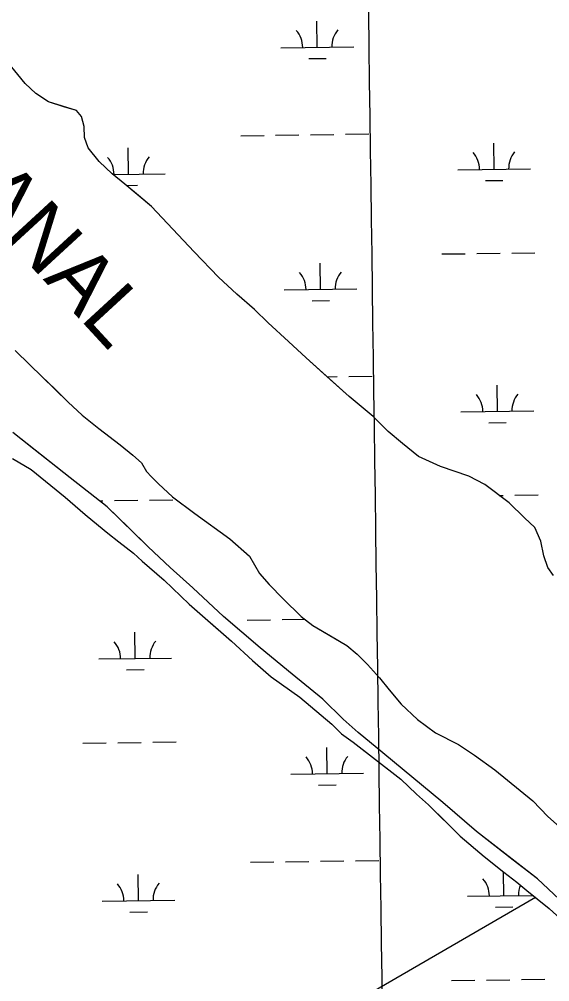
# Model space of a CAD drawing. Extents: x 3753511 to 3791668, y 379550 to 405377.
# Drawn here: x 3783740 to 3784469, y 386459 to 387781 of the extents above; entities that cross this region are included whole.
import ezdxf

# ---------------------------------------------------------------- set-up
doc = ezdxf.new("R2010")
doc.units = 0
for name, color, linetype in [('V-GRID-MAJR', 7, 'Continuous'), ('V-RIVR-IDEN', 7, 'Continuous'), ('V-TOPO-SHOR', 7, 'Continuous'), ('V-WETL-SWMP', 7, 'Continuous')]:
    doc.layers.add(name, color=color, linetype=linetype)

msp = doc.modelspace()

# ---------------------------------------------------------------- linework, layer by layer
at = {"layer": 'V-GRID-MAJR'}
msp.add_spline([(3784253.946, 385328.666), (3784170.23, 391386.958), (3784086.488, 397447.179), (3784002.745, 403507.403), (3784002.718, 403509.328)], degree=3, dxfattribs=at)
at = {"layer": 'V-TOPO-SHOR'}
msp.add_line((3784448.9250000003, 386574.607), (3783909.816065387, 386262.0993850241), dxfattribs=at)
for points in [[(3783829.813, 387618.585), (3783829.0160000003, 387633.663), (3783825.487, 387647.35000000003), (3783818.571, 387655.525), (3783801.393, 387660.88300000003), (3783780.089, 387667.582), (3783762.864, 387679.11), (3783748.366, 387692.715), (3783724.15, 387722.702), (3783697.194, 387751.984), (3783671.6580000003, 387775.106), (3783641.296, 387801.619), (3783616.44, 387825.431), (3783590.18, 387853.348), (3783557.711, 387886.703), (3783523.176, 387921.413), (3783486.5840000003, 387956.108), (3783458.289, 387981.268), (3783433.451, 388002.338), (3783416.889, 388017.298)], [(3784473.772, 387017.135), (3784466.149, 387028.049), (3784460.548, 387043.775), (3784456.284, 387064.313), (3784447.92, 387082.761), (3784434.108, 387096.37), (3784412.702, 387116.78), (3784379.611, 387141.903), (3784357.586, 387153.397), (3784318.4080000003, 387166.68200000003), (3784288.1410000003, 387180.582), (3784266.346, 387198.11100000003), (3784246.755, 387214.556), (3784225.898, 387235.245), (3784192.921, 387262.838), (3784158.552, 387293.846), (3784134.119, 387315.879), (3784109.819, 387338.325), (3784081.7970000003, 387363.896), (3784063.012, 387382.132), (3784038.997, 387403.34500000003), (3784013.4590000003, 387426.878), (3783980.292, 387461.735), (3783921.694, 387523.966), (3783903.7600000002, 387538.916), (3783885.133, 387554.549), (3783867.887, 387568.819), (3783849.936, 387585.826), (3783834.718, 387604.22500000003), (3783829.813, 387618.585)], [(3783734.62, 387325.822), (3783754.645, 387306.087), (3783771.215, 387290.441), (3783789.1720000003, 387272.748), (3783807.127, 387255.055), (3783826.454, 387237.373), (3783849.215, 387219.029), (3783878.86, 387196.624), (3783896.106, 387182.353), (3783907.842, 387171.47000000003), (3783914.782, 387159.866), (3783921.694, 387152.375), (3783931.363, 387142.847), (3783950.69, 387125.165), (3783981.0270000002, 387102.08), (3784029.272, 387067.471), (3784056.186, 387043.673), (3784063.133, 387031.38300000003), (3784070.074, 387019.779), (3784083.2120000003, 387004.794), (3784102.5530000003, 386985.053), (3784127.416, 386960.55700000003), (3784143.273, 386948.332), (3784167.3740000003, 386934.11100000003), (3784190.099, 386920.568), (3784203.896, 386909.015), (3784218.398, 386894.724), (3784234.989, 386876.337), (3784248.1350000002, 386859.978), (3784264.736, 386840.218), (3784286.83, 386819.128), (3784311.648, 386800.80100000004), (3784343.304, 386784.58), (3784365.348, 386770.34500000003), (3784392.923, 386749.979), (3784445.341, 386707.174), (3784466.0670000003, 386686.074), (3784489.531, 386664.994)], [(3784481.302, 386572.379), (3784451.616, 386600.26900000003), (3784418.5160000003, 386626.078), (3784368.179, 386665.471), (3784321.951, 386704.893), (3784239.1750000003, 386773.527), (3784205.377, 386801.386), (3784184.6720000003, 386819.74700000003), (3784157.048, 386846.967), (3784114.97, 386881.621), (3784070.828, 386917.631), (3784020.463, 386960.452), (3783978.35, 386999.905), (3783947.294, 387027.787), (3783916.916, 387056.356), (3783889.983, 387082.896), (3783860.977, 387111.476), (3783809.953, 387150.865), (3783760.3000000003, 387190.26300000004), (3783731.335, 387213.36)], [(3783730.776, 387177.43200000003), (3783756.253, 387162.537), (3783803.154, 387124.489), (3783830.753, 387100.697), (3783848.6890000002, 387085.745), (3783861.796, 387074.87200000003), (3783876.964, 387063.33), (3783896.961, 387047.71), (3783908.698, 387036.826), (3783939.057, 387010.311), (3783973.578, 386977.658), (3783999.111, 386955.222), (3784031.545, 386926.667), (3784060.534, 386900.143), (3784086.069, 386877.705), (3784125.3510000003, 386849.885), (3784169.504, 386812.505), (3784182.628, 386799.576), (3784198.481, 386788.037), (3784221.235, 386770.38), (3784263.989, 386737.10000000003), (3784285.392, 386716.689), (3784301.957, 386701.731), (3784326.127, 386677.912), (3784345.464, 386658.858), (3784378.578, 386630.993), (3784405.477, 386609.253)], [(3784405.477, 386609.253), (3784423.403, 386595.673), (3784437.2, 386584.12), (3784448.9250000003, 386574.607), (3784467.546, 386559.663), (3784488.255, 386540.619)]]:
    msp.add_lwpolyline(points, dxfattribs=at)
at = {"layer": 'V-WETL-SWMP'}
for p, q in [((3784149.380095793, 387742.5315603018), (3784148.893345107, 387778.52826950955)), ((3784099.384666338, 387741.8555176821), (3784199.375525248, 387743.20760292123)), ((3783748.366, 387692.71500000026), (3783724.15, 387722.7020000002)), ((3784137.5898329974, 387726.9397206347), (3784161.5876391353, 387727.26422109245)), ((3783762.864, 387679.1100000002), (3783748.366, 387692.71500000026)), ((3783780.089, 387667.5820000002), (3783762.864, 387679.1100000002)), ((3783818.571, 387655.525), (3783780.089, 387667.5820000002)), ((3783825.488, 387647.3490000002), (3783818.571, 387655.525)), ((3783829.0160000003, 387633.66300000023), (3783825.488, 387647.3490000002)), ((3783829.813, 387618.586), (3783829.0160000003, 387633.66300000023)), ((3783834.718, 387604.22500000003), (3783829.813, 387618.586)), ((3784044.1693247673, 387621.02691414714), (3784076.166399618, 387621.4595814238)), ((3784092.164937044, 387621.6759150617), (3784124.1620118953, 387622.10858233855)), ((3784140.1605493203, 387622.324915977), (3784172.157624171, 387622.7575832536)), ((3784188.1561615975, 387622.97391689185), (3784220.1532364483, 387623.40658416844)), ((3783849.937, 387585.826), (3783834.718, 387604.22500000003)), ((3783890.277531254, 387568.19933690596), (3783889.7907805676, 387604.1960461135)), ((3784392.1396513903, 387574.98556088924), (3784391.6529007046, 387610.9822700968)), ((3783867.8880000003, 387568.81900000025), (3783849.937, 387585.82600000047)), ((3784342.1442219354, 387574.30951826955), (3784442.1350808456, 387575.661603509)), ((3783885.133, 387554.548), (3783867.8880000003, 387568.81900000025)), ((3783868.9847224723, 387567.91141366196), (3783940.2729607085, 387568.87537952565)), ((3784380.3493885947, 387559.3937212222), (3784404.3471947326, 387559.7182216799)), ((3783921.6950000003, 387523.966), (3783885.133, 387554.548)), ((3783887.3103133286, 387552.7268032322), (3783902.485074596, 387552.93199769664)), ((3783980.292, 387461.73600000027), (3783921.6950000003, 387523.966)), ((3784013.458, 387426.878), (3783980.292, 387461.73600000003)), ((3784320.2991007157, 387458.5715739), (3784352.296175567, 387459.0042411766)), ((3784368.2947129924, 387459.22057481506), (3784400.291787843, 387459.6532420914)), ((3784416.2903252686, 387459.8695757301), (3784448.28740012, 387460.3022430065)), ((3784153.8781453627, 387409.8869704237), (3784153.391394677, 387445.88367963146)), ((3784038.998, 387403.34500000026), (3784013.458, 387426.87800000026)), ((3784063.0130000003, 387382.1310000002), (3784038.998, 387403.34500000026)), ((3784103.882715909, 387409.210927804), (3784203.873574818, 387410.5630130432)), ((3784142.0878825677, 387394.2951307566), (3784166.0856887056, 387394.6196312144)), ((3784081.796, 387363.896), (3784063.0130000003, 387382.1310000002)), ((3784109.8200000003, 387338.32400000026), (3784081.796, 387363.896)), ((3784134.1180000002, 387315.879), (3784109.8200000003, 387338.32400000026)), ((3784192.9220000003, 387262.83700000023), (3784134.1180000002, 387315.87900000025)), ((3784162.889361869, 387289.92684408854), (3784176.655673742, 387290.1129933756)), ((3784192.6542111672, 387290.32932701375), (3784224.6512860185, 387290.76199429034)), ((3784396.6377009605, 387242.34097101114), (3784396.1509502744, 387278.3376802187)), ((3784225.897, 387235.2450000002), (3784192.9220000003, 387262.83700000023)), ((3784346.642271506, 387241.66492839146), (3784446.633130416, 387243.0170136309)), ((3784246.754, 387214.55700000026), (3784225.897, 387235.2450000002)), ((3784384.847438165, 387226.7491313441), (3784408.845244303, 387227.0736318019)), ((3784266.346, 387198.11), (3784246.754, 387214.55700000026)), ((3784288.14, 387180.582), (3784266.346, 387198.10999999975)), ((3783730.776, 387177.431), (3783756.253, 387162.536)), ((3784318.409, 387166.68200000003), (3784288.14, 387180.582)), ((3784357.586, 387153.39700000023), (3784318.409, 387166.68200000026)), ((3783756.253, 387162.536), (3783803.154, 387124.489)), ((3784379.61, 387141.9040000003), (3784357.586, 387153.39700000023)), ((3784412.703, 387116.78100000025), (3784379.61, 387141.9040000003)), ((3783803.154, 387124.489), (3783830.753, 387100.697)), ((3784399.328020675, 387126.93479704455), (3784404.789837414, 387127.00865221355)), ((3784420.788374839, 387127.22498585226), (3784452.7854496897, 387127.6576531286)), ((3783850.565220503, 387119.51437791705), (3783854.9321050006, 387119.5734273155)), ((3783870.930642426, 387119.7897609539), (3783902.9277172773, 387120.2224282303)), ((3783918.9262547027, 387120.438761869), (3783950.9233295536, 387120.87142914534)), ((3784434.1070000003, 387096.371), (3784412.703, 387116.78100000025)), ((3783830.753, 387100.697), (3783861.796, 387074.873)), ((3784447.92, 387082.761), (3784434.1070000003, 387096.371)), ((3783861.796, 387074.87300000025), (3783876.964, 387063.33000000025)), ((3784456.2830000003, 387064.31200000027), (3784447.92, 387082.761)), ((3783876.964, 387063.33000000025), (3783896.961, 387047.70900000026)), ((3784460.548, 387043.776), (3784456.2830000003, 387064.31200000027)), ((3783896.961, 387047.70900000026), (3783908.697, 387036.826)), ((3784466.149, 387028.048), (3784460.548, 387043.776)), ((3783908.697, 387036.826), (3783939.058, 387010.31200000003)), ((3784473.771, 387017.13500000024), (3784466.149, 387028.048)), ((3783939.058, 387010.31200000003), (3783973.579, 386977.658)), ((3783973.579, 386977.658), (3784031.545, 386926.666)), ((3784053.165423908, 386955.73773439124), (3784085.1624987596, 386956.1704016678)), ((3784101.1610361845, 386956.3867353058), (3784132.2781707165, 386956.8075039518)), ((3783899.2736303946, 386902.91015715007), (3783898.7868797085, 386938.90686635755)), ((3784031.545, 386926.666), (3784060.535, 386900.142)), ((3783849.2782009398, 386902.2341145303), (3783949.26905985, 386903.58619976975)), ((3784060.535, 386900.142), (3784086.068, 386877.70600000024)), ((3783887.4833675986, 386887.31831748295), (3783911.4811737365, 386887.64281794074)), ((3784086.068, 386877.70600000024), (3784125.352, 386849.886)), ((3784125.352, 386849.886), (3784169.505, 386812.504)), ((3784169.505, 386812.504), (3784182.627, 386799.575)), ((3784182.627, 386799.575), (3784198.481, 386788.037)), ((3783827.4330797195, 386786.496170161), (3783859.430154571, 386786.92883743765)), ((3783875.4286919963, 386787.14517107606), (3783907.425766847, 386787.5778383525)), ((3783923.4243042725, 386787.7941719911), (3783955.421379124, 386788.2268392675)), ((3784162.8742445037, 386744.597790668), (3784162.3874938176, 386780.5944998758)), ((3784198.481, 386788.037), (3784263.988, 386737.10000000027)), ((3784112.8788150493, 386743.92174804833), (3784212.869673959, 386745.2738332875)), ((3784151.0839817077, 386729.00595100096), (3784175.0817878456, 386729.3304514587)), ((3784263.988, 386737.10000000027), (3784285.392, 386716.69)), ((3784285.392, 386716.69), (3784301.9560000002, 386701.7300000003)), ((3784301.9560000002, 386701.7300000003), (3784345.465, 386658.85800000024)), ((3784345.465, 386658.85800000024), (3784378.579, 386630.99300000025)), ((3784057.663473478, 386623.0931445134), (3784089.6605483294, 386623.52581179)), ((3784105.6590857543, 386623.74214542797), (3784137.6561606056, 386624.1748127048)), ((3784153.6546980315, 386624.39114634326), (3784185.6517728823, 386624.82381361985)), ((3784201.650310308, 386625.040147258), (3784233.647385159, 386625.4728145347)), ((3784378.579, 386630.993), (3784405.477, 386609.253)), ((3784405.6338001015, 386577.0517912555), (3784405.1952937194, 386609.4806858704)), ((3784405.477, 386609.25300000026), (3784423.403, 386595.67300000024)), ((3783903.771679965, 386570.2655672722), (3783903.2849292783, 386606.26227647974)), ((3784423.403, 386595.67300000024), (3784437.2, 386584.1200000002)), ((3784437.2, 386584.1200000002), (3784467.546, 386559.662)), ((3783853.77625051, 386569.5895246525), (3783953.7671094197, 386570.9416098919)), ((3784355.6383706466, 386576.3757486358), (3784445.304237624, 386577.588218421)), ((3783891.981417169, 386554.6737276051), (3783915.9792233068, 386554.9982280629)), ((3784393.843537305, 386561.4599515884), (3784417.841343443, 386561.78445204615)), ((3784467.546, 386559.662), (3784488.255, 386540.618)), ((3784429.7844739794, 386461.9358060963), (3784461.7815488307, 386462.3684733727)), ((3784333.793249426, 386460.63780426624), (3784365.790324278, 386461.07047154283)), ((3784381.788861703, 386461.2868051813), (3784413.785936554, 386461.71947245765))]:
    msp.add_line(p, q, dxfattribs=at)
for points in [[(3783734.619, 387325.821), (3783754.646, 387306.087), (3783771.216, 387290.441), (3783807.128, 387255.055), (3783826.455, 387237.37200000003), (3783849.215, 387219.029), (3783878.86, 387196.623), (3783896.106, 387182.353), (3783907.841, 387171.47000000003), (3783914.782, 387159.866), (3783921.694, 387152.375), (3783931.362, 387142.848), (3783950.6890000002, 387125.165), (3783981.026, 387102.079), (3784029.272, 387067.47000000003), (3784056.186, 387043.673), (3784063.133, 387031.38300000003), (3784070.074, 387019.779), (3784083.211, 387004.793), (3784102.5530000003, 386985.054), (3784127.415, 386960.556), (3784143.274, 386948.332), (3784190.099, 386920.568), (3784203.896, 386909.015), (3784218.399, 386894.724), (3784234.989, 386876.336), (3784248.136, 386859.978), (3784264.736, 386840.219), (3784286.83, 386819.128), (3784311.647, 386800.8), (3784343.304, 386784.58), (3784365.348, 386770.34500000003), (3784392.9220000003, 386749.98), (3784445.342, 386707.175), (3784466.066, 386686.074), (3784489.531, 386664.994)], [(3784481.302, 386572.378), (3784451.616, 386600.268), (3784368.1780000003, 386665.47000000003), (3784321.952, 386704.893), (3784239.1750000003, 386773.527), (3784205.376, 386801.387), (3784184.6720000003, 386819.746), (3784157.048, 386846.966), (3784114.971, 386881.62), (3784070.827, 386917.631), (3784020.463, 386960.452), (3783978.3510000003, 386999.906), (3783947.294, 387027.786), (3783916.917, 387056.357), (3783860.977, 387111.477), (3783809.953, 387150.865), (3783731.335, 387213.36)]]:
    msp.add_lwpolyline(points, dxfattribs=at)
for centre, radius, start, end in [((3784094.135789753, 387742.25938849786), 35.24628790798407, 0.0028913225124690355, 41.5465496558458), ((3784204.6115623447, 387743.7532516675), 35.246287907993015, 140.00288831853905, 181.54654665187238), ((3783835.033225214, 387567.92716510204), 35.24628790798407, 0.0028913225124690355, 41.5465496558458), ((3783945.508997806, 387569.42102827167), 35.246287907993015, 140.00288831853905, 181.54654665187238), ((3784336.8953453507, 387574.7133890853), 35.24628790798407, 0.0028913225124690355, 41.5465496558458), ((3784447.3711179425, 387576.20725225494), 35.246287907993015, 140.00288831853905, 181.54654665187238), ((3784098.633839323, 387409.61479861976), 35.24628790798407, 0.0028913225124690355, 41.5465496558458), ((3784209.1096119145, 387411.10866178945), 35.246287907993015, 140.00288831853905, 181.54654665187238), ((3784341.3933949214, 387242.0687992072), 35.24628790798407, 0.0028913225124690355, 41.5465496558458), ((3784451.8691675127, 387243.5626623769), 35.246287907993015, 140.00288831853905, 181.54654665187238), ((3783844.029324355, 386902.6379853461), 35.24628790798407, 0.0028913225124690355, 41.5465496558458), ((3783954.505096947, 386904.13184851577), 35.246287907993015, 140.00288831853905, 181.54654665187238), ((3784107.6299384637, 386744.3256188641), 35.24628790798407, 0.0028913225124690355, 41.5465496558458), ((3784218.1057110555, 386745.8194820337), 35.246287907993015, 140.00288831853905, 181.54654665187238), ((3784350.3894940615, 386576.77961945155), 35.24628790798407, 0.0028913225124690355, 41.5465496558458), ((3783848.5273739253, 386569.9933954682), 35.24628790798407, 0.0028913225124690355, 41.5465496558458), ((3783959.003146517, 386571.4872586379), 35.246287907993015, 140.00288831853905, 181.54654665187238), ((3784460.8652666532, 386578.2734826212), 35.246287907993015, 157.74944816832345, 181.54654665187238)]:
    msp.add_arc(centre, radius, start, end, dxfattribs=at)

# ---------------------------------------------------------------- texts
at = {"layer": 'V-RIVR-IDEN'}
msp.add_text('CANAL', height=82.99983200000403, rotation=312.6627196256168, dxfattribs=at).set_placement((3783613.248734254, 387596.23978185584))

doc.saveas('drawing.dxf')
